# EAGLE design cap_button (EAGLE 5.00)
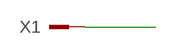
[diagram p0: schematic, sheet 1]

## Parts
X1  PIN  [PIN]

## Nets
S1: X1.P$1(KL)

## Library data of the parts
X1 = AVRRemote:PIN

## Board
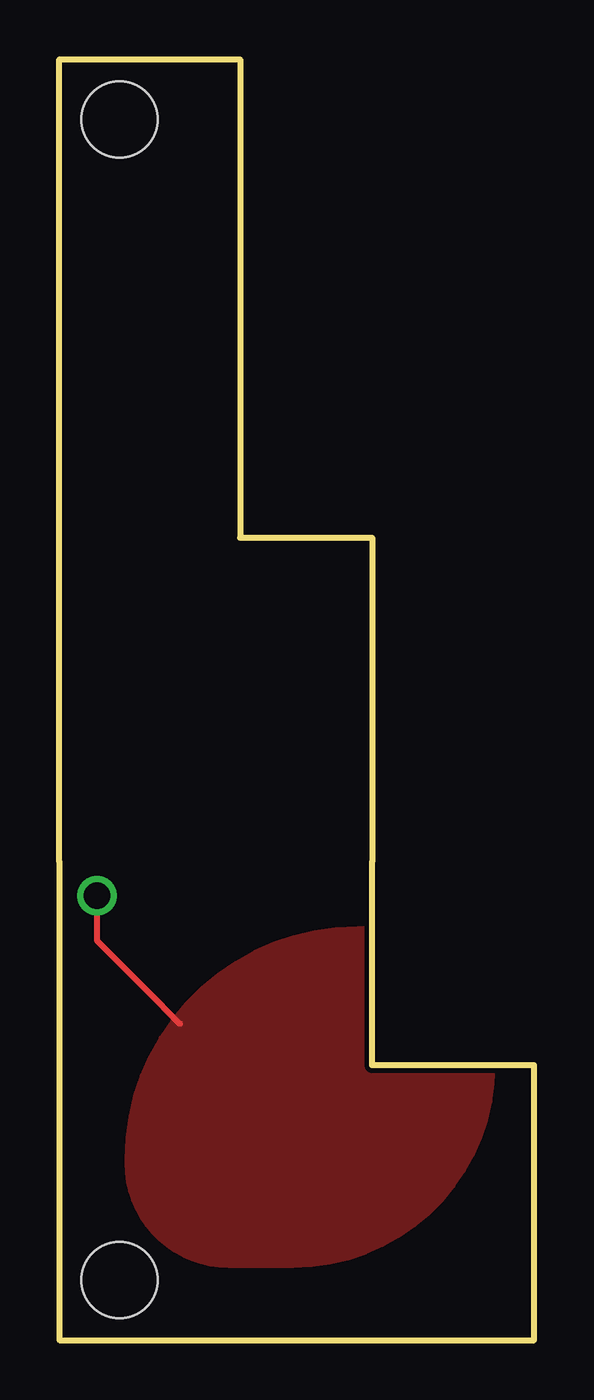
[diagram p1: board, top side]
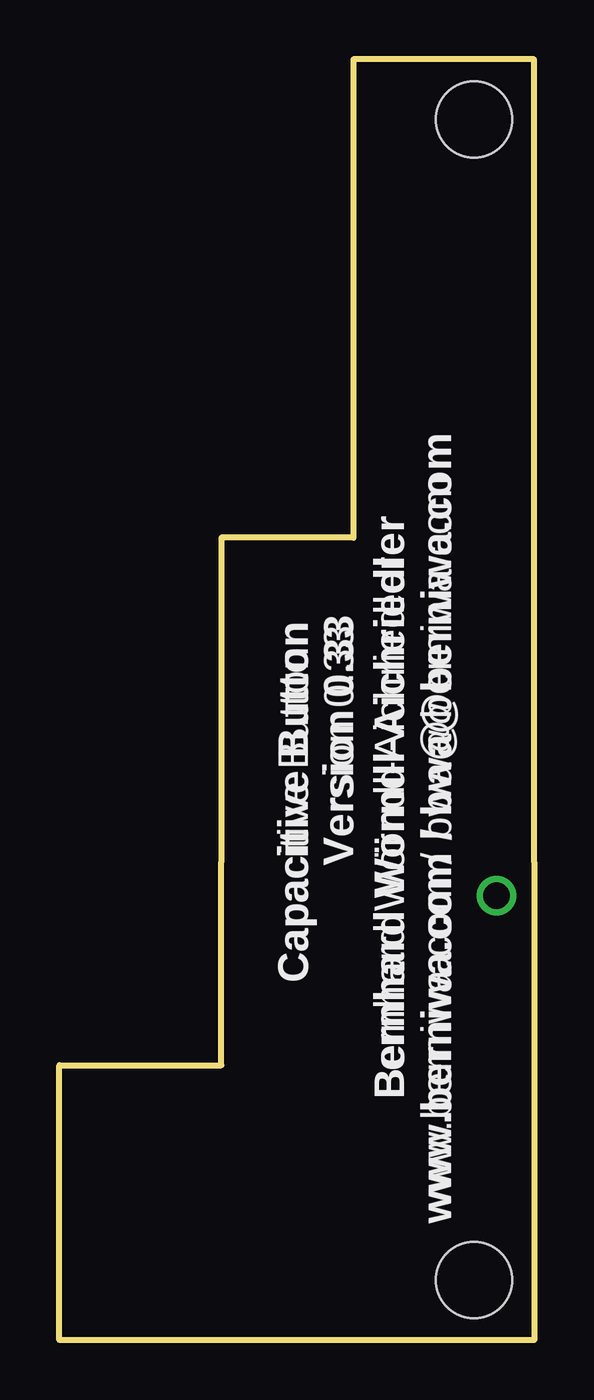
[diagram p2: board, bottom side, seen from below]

Size 20 x 53.98 mm. Coordinates in mm from the lower left corner, seen from the top.
Outline: 0,0 20,0 20,11.59 13.18,11.59 13.18,20.16 13.18,33.81 7.62,33.81 7.62,53.98 0,53.98 0,20.16 0,0
Copper layers (1*16): Top 0.035mm / dielectric 1.5mm / Bottom 0.035mm
Design rules "default *": minimum track width 10mil, minimum drill 24mil, track to track 8mil, track to pad 8mil, pad to pad 8mil, via to via 8mil, smd to smd 8mil, copper to edge 8mil, drill to drill 8mil, minimum pad ring 10mil, minimum via ring 8mil, stop-mask expansion 4mil, vias tented up to drill 0mil, thermal gap 10mil
Holes 3.2 mm at 2.54,2.54 2.54,51.44

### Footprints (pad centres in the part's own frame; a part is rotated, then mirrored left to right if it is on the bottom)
PIN = drill 1.1 round: P$1 0,0

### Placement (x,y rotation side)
X1  1.59,18.73 0 top

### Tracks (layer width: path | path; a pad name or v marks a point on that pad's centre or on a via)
S1
  Top 0.254: 5.08,13.34 3.65,14.76 1.59,16.83 X1.P$1
  pour Top: 13.18,17.3 12.54,17.3 arc90 2.86,7.62 2.86,7.46 arc90 7.14,3.17 9.84,3.17 arc90 18.26,11.59 13.18,11.59

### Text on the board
bPlace: Version 0.33 | Capacitive Button | Bernhard Wörndl-Aichriedler | www.berniwa.com / bwa@berniwa.com
_bsilk: Version 0.33 | Capacitive Button | Bernhard Wörndl-Aichriedler | www.berniwa.com / bwa@berniwa.com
